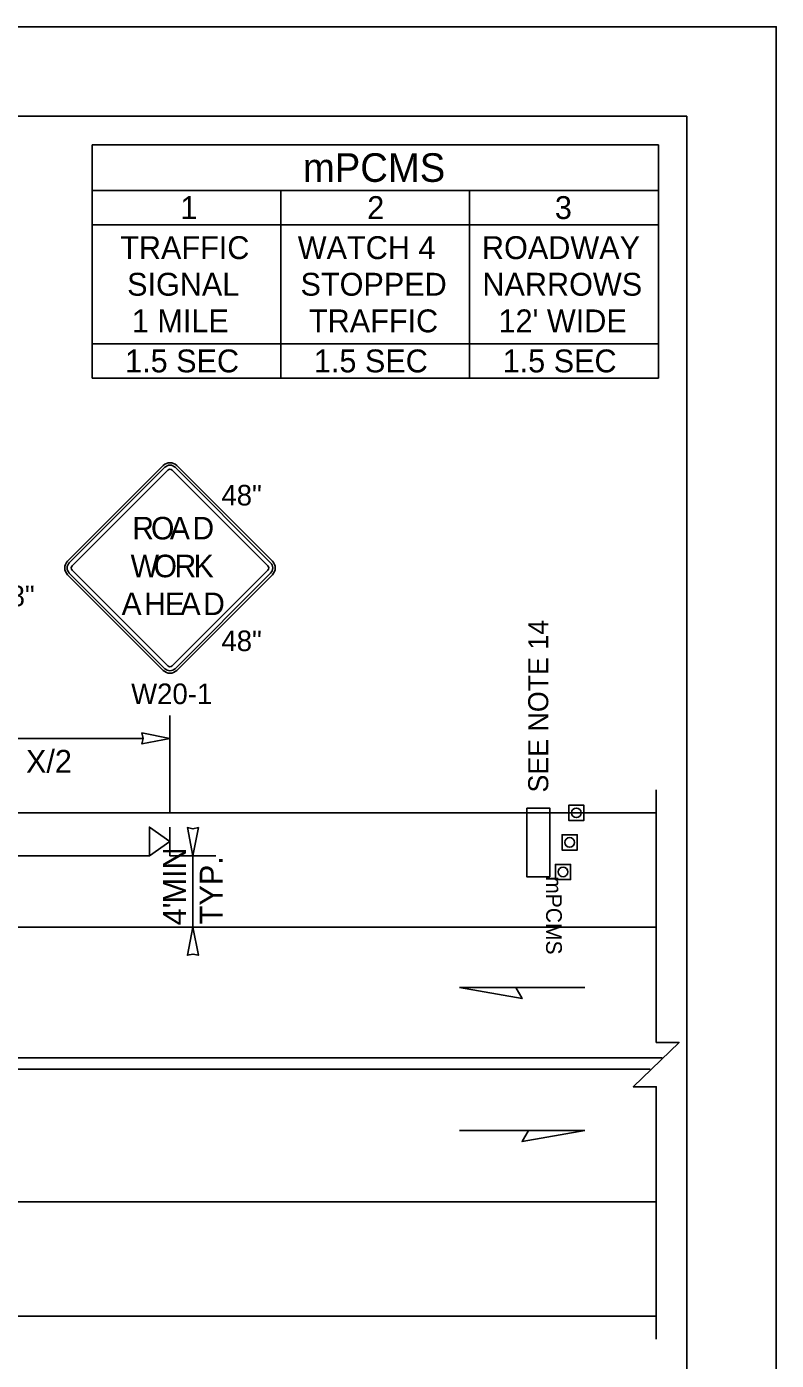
# Model space of a CAD drawing. Extents: x 99979.8 to 100075.7, y 99995 to 100010.7.
# Drawn here: x 100033.441 to 100036.062, y 100006.025 to 100010.687 of the extents above; entities that cross this region are included whole.
import ezdxf

# ---------------------------------------------------------------- set-up
doc = ezdxf.new("R2010")
doc.units = 0
for name, color, linetype in [('RD_ED_ShoulderPavedEdge', 7, 'Continuous'), ('RD_MK_LineDblYellowCenter', 7, 'Continuous'), ('RD_MK_LineEdgeWhite', 7, 'Continuous'), ('RD_MK_LineNoPass', 7, 'Continuous'), ('RD_MK_LineSkipCenter', 7, 'Continuous'), ('SH_GI_PlotLimits', 7, 'Continuous'), ('SH_GI_SheetBorder', 7, 'Continuous'), ('TR_SN_ConstructionSigns', 7, 'Continuous'), ('TR_WZ_PCMS', 7, 'Continuous'), ('TR_WZ_PortableChangeMessageSign', 7, 'Continuous'), ('TR_WZ_PortableSignMountBlk-Org', 7, 'Continuous'), ('TR_WZ_TrafficCone', 7, 'Continuous'), ('TR_WZ_WorkZoneDetails', 7, 'Continuous'), ('TR_WZ_WorkZoneTextCurrent', 7, 'Continuous')]:
    doc.layers.add(name, color=color, linetype=linetype)

msp = doc.modelspace()

# ---------------------------------------------------------------- linework, layer by layer
at = {"layer": 'RD_ED_ShoulderPavedEdge'}
for p, q in [((100035.6424, 100007.9393), (100020.3, 100007.9393)), ((100020.3, 100006.1793), (100035.6425, 100006.1793))]:
    msp.add_line(p, q, dxfattribs=at)
at = {"layer": 'RD_MK_LineDblYellowCenter'}
for p, q in [((100035.6631, 100007.0826), (100034.6924, 100007.0826)), ((100035.6218, 100007.0426), (100034.4924, 100007.0426))]:
    msp.add_line(p, q, dxfattribs=at)
at = {"layer": 'RD_MK_LineEdgeWhite'}
for p, q in [((100024.8112, 100007.5393), (100035.6425, 100007.5393)), ((100025.5008, 100006.5793), (100035.6425, 100006.5793))]:
    msp.add_line(p, q, dxfattribs=at)
at = {"layer": 'RD_MK_LineNoPass'}
msp.add_line((100034.4924, 100007.0426), (100033.1715, 100007.0426), dxfattribs=at)
at = {"layer": 'RD_MK_LineSkipCenter'}
msp.add_lwpolyline([(100025.5008, 100007.0826), (100034.6924, 100007.0826)], dxfattribs=at)
at = {"layer": 'SH_GI_PlotLimits'}
msp.add_lwpolyline([(100019.0625, 99999.6875), (100036.0625, 99999.6875), (100036.0625, 100010.6875), (100019.0625, 100010.6875)], close=True, dxfattribs=at)
at = {"layer": 'SH_GI_SheetBorder'}
for p, q in [((100020, 100010.375), (100035.75, 100010.375)), ((100035.75, 100010.375), (100035.75, 100000))]:
    msp.add_line(p, q, dxfattribs=at)
at = {"layer": 'TR_SN_ConstructionSigns'}
for p, q in [((100033.9186, 100009.1531), (100033.5845, 100008.819)), ((100034.3005, 100008.819), (100033.9663, 100009.1531)), ((100033.9246, 100009.1472), (100033.5905, 100008.8131)), ((100033.6004, 100008.8031), (100033.9345, 100009.1372)), ((100033.9504, 100009.1372), (100034.2845, 100008.8031)), ((100034.2945, 100008.8131), (100033.9604, 100009.1472)), ((100033.9345, 100008.4531), (100033.6004, 100008.7872)), ((100034.2845, 100008.7872), (100033.9504, 100008.4531)), ((100033.5845, 100008.7713), (100033.9186, 100008.4372)), ((100033.5905, 100008.7773), (100033.9246, 100008.4432)), ((100033.9604, 100008.4432), (100034.2945, 100008.7773)), ((100033.9663, 100008.4372), (100034.3005, 100008.7713))]:
    msp.add_line(p, q, dxfattribs=at)
for centre, radius, start, end in [((100033.9425, 100009.1293), 0.0338, 45, 135), ((100033.9425, 100009.1293), 0.0253, 45, 135), ((100033.9425, 100009.1293), 0.0113, 45, 135), ((100033.6084, 100008.7952), 0.0338, 135, 225), ((100033.6084, 100008.7952), 0.0253, 135, 225), ((100033.6084, 100008.7952), 0.0113, 135, 225), ((100034.2766, 100008.7952), 0.0113, 315, 45), ((100034.2766, 100008.7952), 0.0253, 315, 45), ((100034.2766, 100008.7952), 0.0338, 315, 45), ((100033.9425, 100008.4611), 0.0113, 225, 315), ((100033.9425, 100008.4611), 0.0338, 225, 315), ((100033.9425, 100008.4611), 0.0253, 225, 315)]:
    msp.add_arc(centre, radius, start, end, dxfattribs=at)
at = {"layer": 'TR_WZ_PCMS'}
msp.add_lwpolyline([(100035.19, 100007.9559), (100035.19, 100007.7159), (100035.27, 100007.7159), (100035.27, 100007.9559)], close=True, dxfattribs=at)
msp.add_lwpolyline([(100035.19, 100007.9559), (100035.19, 100007.7159), (100035.27, 100007.7159), (100035.27, 100007.9559), (100035.19, 100007.9559)], dxfattribs=at)
at = {"layer": 'TR_WZ_PortableChangeMessageSign'}
for p, q in [((100033.67, 100010.275), (100035.65, 100010.275)), ((100033.67, 100009.459), (100033.67, 100010.275)), ((100035.65, 100009.459), (100035.65, 100010.275)), ((100035.65, 100010.115), (100033.67, 100010.115)), ((100034.33, 100009.459), (100034.33, 100010.115)), ((100034.99, 100009.459), (100034.99, 100010.115)), ((100034.33, 100009.995), (100033.67, 100009.995)), ((100034.99, 100009.995), (100034.33, 100009.995)), ((100035.65, 100009.995), (100034.99, 100009.995)), ((100033.67, 100009.579), (100034.33, 100009.579)), ((100034.33, 100009.579), (100034.99, 100009.579)), ((100034.99, 100009.579), (100035.65, 100009.579)), ((100035.65, 100009.459), (100033.67, 100009.459))]:
    msp.add_line(p, q, dxfattribs=at)
at = {"layer": 'TR_WZ_PortableSignMountBlk-Org'}
msp.add_line((100033.9425, 100007.8893), (100033.9425, 100007.7893), dxfattribs=at)
msp.add_lwpolyline([(100033.9425, 100007.8394), (100033.8707, 100007.7893), (100033.8707, 100007.8893)], close=True, dxfattribs=at)
at = {"layer": 'TR_WZ_TrafficCone'}
for points in [[(100035.39, 100007.9126), (100035.3367, 100007.9126), (100035.3367, 100007.9659), (100035.39, 100007.9659), (100035.39, 100007.9126)], [(100035.39, 100007.9659), (100035.3367, 100007.9659), (100035.3367, 100007.9126), (100035.39, 100007.9126), (100035.39, 100007.9659)], [(100035.3667, 100007.8092), (100035.3133, 100007.8092), (100035.3133, 100007.8626), (100035.3667, 100007.8626), (100035.3667, 100007.8092)], [(100035.3667, 100007.8626), (100035.3133, 100007.8626), (100035.3133, 100007.8092), (100035.3667, 100007.8092), (100035.3667, 100007.8626)], [(100035.3433, 100007.7059), (100035.29, 100007.7059), (100035.29, 100007.7592), (100035.3433, 100007.7592), (100035.3433, 100007.7059)], [(100035.3433, 100007.7592), (100035.29, 100007.7592), (100035.29, 100007.7059), (100035.3433, 100007.7059), (100035.3433, 100007.7592)]]:
    msp.add_lwpolyline(points, dxfattribs=at)
for centre in [(100035.3633, 100007.9392), (100035.34, 100007.8359), (100035.3167, 100007.7326)]:
    msp.add_circle(centre, 0.0167, dxfattribs=at)
at = {"layer": 'TR_WZ_WorkZoneDetails'}
for p, q in [((100033.9425, 100007.9393), (100033.9425, 100008.2793)), ((100033.1862, 100008.1993), (100033.8487, 100008.1993)), ((100026.7814, 100007.7893), (100033.8707, 100007.7893)), ((100033.9425, 100007.7893), (100034.1025, 100007.7893)), ((100034.0225, 100007.7893), (100034.0225, 100007.5394)), ((100033.9425, 100007.5394), (100034.1025, 100007.5394)), ((100035.1514, 100007.3286), (100035.3925, 100007.3286)), ((100035.1959, 100006.8286), (100034.9548, 100006.8286))]:
    msp.add_line(p, q, dxfattribs=at)
for points in [[(100033.9425, 100008.1993), (100033.8442, 100008.18), (100033.8487, 100008.1993), (100033.8442, 100008.2186)], [(100034.0225, 100007.7893), (100034.0032, 100007.8876), (100034.0225, 100007.883), (100034.0418, 100007.8876)], [(100034.0225, 100007.5394), (100034.0032, 100007.4411), (100034.0225, 100007.4457), (100034.0418, 100007.4411)], [(100034.9548, 100007.3286), (100035.1737, 100007.29), (100035.1514, 100007.3286)], [(100035.3925, 100006.8286), (100035.1737, 100006.79), (100035.1959, 100006.8286)]]:
    msp.add_lwpolyline(points, close=True, dxfattribs=at)
msp.add_lwpolyline([(100035.6425, 100006.0993), (100035.6425, 100006.9819), (100035.5624, 100006.9819), (100035.7225, 100007.1367), (100035.6425, 100007.1367), (100035.6425, 100008.0193)], dxfattribs=at)

# ---------------------------------------------------------------- texts
at = {"layer": 'TR_SN_ConstructionSigns'}
for s, p in [('48"', (100034.1223, 100009.0137)), ('48"', (100033.3282, 100008.6613)), ('48"', (100034.1223, 100008.5046)), ('W20-1', (100033.8066, 100008.3193))]:
    msp.add_text(s, height=0.072, rotation=360, dxfattribs=at).set_placement(p)
for s, p in [('R', (100033.8106, 100008.895)), ('O', (100033.8759, 100008.895)), ('A', (100033.9421, 100008.895)), ('D', (100034.0208, 100008.895)), ('W', (100033.8047, 100008.7628)), ('O', (100033.885, 100008.7628)), ('R', (100033.9582, 100008.7628)), ('K', (100034.0252, 100008.7628)), ('A', (100033.7732, 100008.6306)), ('H', (100033.8519, 100008.6306)), ('E', (100033.9244, 100008.6306)), ('A', (100033.9795, 100008.6306)), ('D', (100034.0582, 100008.6306))]:
    msp.add_text(s, height=0.0788, dxfattribs=at).set_placement(p)
at = {"layer": 'TR_WZ_PCMS'}
msp.add_text('mPCMS', height=0.055, rotation=270, dxfattribs=at).set_placement((100035.2575, 100007.7176))
at = {"layer": 'TR_WZ_PortableChangeMessageSign'}
for s, height, p in [('mPCMS', 0.1, (100034.4072, 100010.145)), ('1', 0.08, (100033.9789, 100010.015)), ('2', 0.08, (100034.6321, 100010.015)), ('3', 0.08, (100035.2882, 100010.015)), ('TRAFFIC', 0.08, (100033.7684, 100009.875)), ('WATCH 4', 0.08, (100034.3892, 100009.875)), ('ROADWAY', 0.08, (100035.0333, 100009.875)), ('SIGNAL', 0.08, (100033.7925, 100009.747)), ('STOPPED', 0.08, (100034.3989, 100009.747)), ('NARROWS', 0.08, (100035.0348, 100009.747)), ('1 MILE', 0.08, (100033.8091, 100009.619)), ('TRAFFIC', 0.08, (100034.4284, 100009.619)), ("12' WIDE", 0.08, (100035.0912, 100009.619)), ('1.5 SEC', 0.08, (100033.7856, 100009.479)), ('1.5 SEC', 0.08, (100034.4456, 100009.479)), ('1.5 SEC', 0.08, (100035.1056, 100009.479))]:
    msp.add_text(s, height=height, rotation=360, dxfattribs=at).set_placement(p)
at = {"layer": 'TR_WZ_WorkZoneTextCurrent'}
for s, height, p in [('SEE NOTE 14', 0.07, (100035.265, 100008.0103)), ('MIN', 0.08, (100033.9985, 100007.6224)), ('TYP.', 0.08, (100034.1265, 100007.5497)), ("4'", 0.08, (100033.9985, 100007.546))]:
    msp.add_text(s, height=height, rotation=90, dxfattribs=at).set_placement(p)
msp.add_text('X/2', height=0.08, dxfattribs=at).set_placement((100033.439, 100008.0793))

doc.saveas('drawing.dxf')
